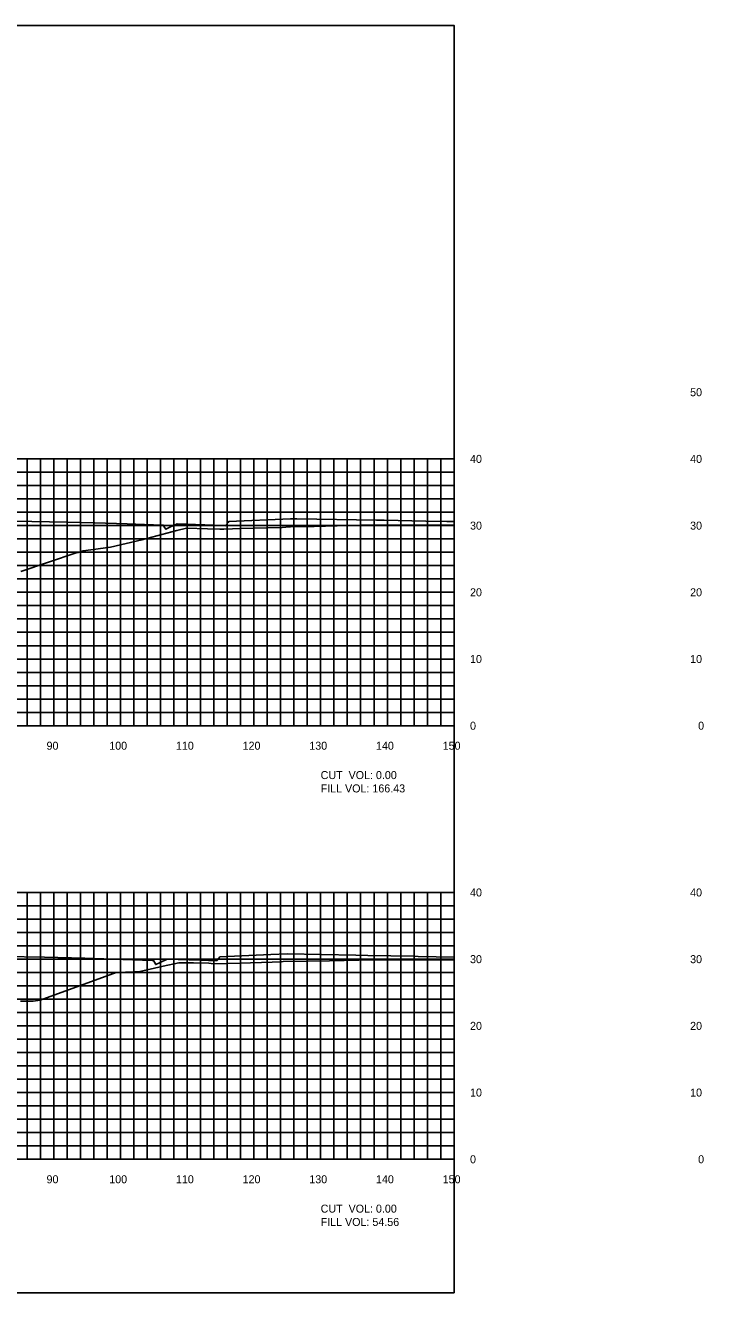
# Model space of a CAD drawing. Extents: x 1797518 to 1804843, y 248068 to 251132.
# Drawn here: x 1803736.7 to 1803838.4, y 250079.4 to 250269.4 of the extents above; entities that cross this region are included whole.
import ezdxf

# ---------------------------------------------------------------- set-up
doc = ezdxf.new("R2010")
doc.units = 0
for name, color, linetype in [('10', 7, 'Continuous'), ('31', 7, 'Continuous'), ('60', 7, 'Continuous'), ('ANNO-TXT', 7, 'Continuous'), ('CL-CNST', 7, 'Continuous'), ('Level 62', 7, 'Continuous'), ('M-ROADS', 7, 'Continuous')]:
    doc.layers.add(name, color=color, linetype=linetype)

msp = doc.modelspace()

# ---------------------------------------------------------------- linework, layer by layer
msp.add_lwpolyline([(1803501, 250079.43), (1803801, 250079.43), (1803801, 250269.43), (1803501, 250269.43)], close=True)
at = {"layer": '60'}
for p, q in [((1803801, 250164.43), (1803801, 250204.43)), ((1803801.06, 250204.43), (1803801, 250204.43)), ((1803801.06, 250194.43), (1803801, 250194.43)), ((1803801.06, 250184.43), (1803801, 250184.43)), ((1803801.06, 250174.43), (1803801, 250174.43)), ((1803501, 250164.43), (1803801, 250164.43)), ((1803741, 250164.37), (1803741, 250164.43)), ((1803751, 250164.37), (1803751, 250164.43)), ((1803761, 250164.37), (1803761, 250164.43)), ((1803771, 250164.37), (1803771, 250164.43)), ((1803781, 250164.37), (1803781, 250164.43)), ((1803791, 250164.37), (1803791, 250164.43)), ((1803801, 250164.37), (1803801, 250164.43)), ((1803801.06, 250164.43), (1803801, 250164.43)), ((1803801, 250099.43), (1803801, 250139.43)), ((1803801.06, 250139.43), (1803801, 250139.43)), ((1803801.06, 250129.43), (1803801, 250129.43)), ((1803801.06, 250119.43), (1803801, 250119.43)), ((1803801.06, 250109.43), (1803801, 250109.43)), ((1803501, 250099.43), (1803801, 250099.43)), ((1803741, 250099.37), (1803741, 250099.43)), ((1803751, 250099.37), (1803751, 250099.43)), ((1803761, 250099.37), (1803761, 250099.43)), ((1803771, 250099.37), (1803771, 250099.43)), ((1803781, 250099.37), (1803781, 250099.43)), ((1803791, 250099.37), (1803791, 250099.43)), ((1803801, 250099.37), (1803801, 250099.43)), ((1803801.06, 250099.43), (1803801, 250099.43))]:
    msp.add_line(p, q, dxfattribs=at)
at = {"layer": 'CL-CNST'}
for points in [[(1803735.03, 250195.08), (1803742.97, 250194.94), (1803747.14, 250194.86), (1803751.98, 250194.68), (1803757.22, 250194.49), (1803757.3, 250194.49), (1803757.44, 250194.48), (1803757.56, 250194.26), (1803757.77, 250193.88), (1803758.38, 250194.18), (1803759.49, 250194.71), (1803765.04, 250194.49), (1803766.67, 250194.42), (1803767.11, 250194.92), (1803767.21, 250195.04), (1803776.48, 250195.43), (1803777.28, 250195.47), (1803777.41, 250195.46), (1803789.36, 250195.26), (1803790.5, 250195.24), (1803796.75, 250195.12), (1803799.93, 250195.07), (1803801, 250195.05)], [(1803733.53, 250129.82), (1803739.57, 250129.71), (1803745.64, 250129.59), (1803749.89, 250129.44), (1803755.74, 250129.23), (1803755.82, 250129.22), (1803755.95, 250129.22), (1803756.08, 250128.99), (1803756.28, 250128.62), (1803756.92, 250128.92), (1803758.01, 250129.45), (1803762.92, 250129.26), (1803765.36, 250129.17), (1803765.74, 250129.6), (1803765.9, 250129.79), (1803773.52, 250130.11), (1803775.98, 250130.22), (1803786.28, 250130.03), (1803788.06, 250129.99), (1803794.99, 250129.87), (1803795.62, 250129.85), (1803801, 250129.75)]]:
    msp.add_lwpolyline(points, dxfattribs=at)
at = {"layer": 'Level 62'}
for p, q in [((1803501, 250204.43), (1803801, 250204.43)), ((1803737, 250164.43), (1803737, 250204.43)), ((1803739, 250164.43), (1803739, 250204.43)), ((1803741, 250164.43), (1803741, 250204.43)), ((1803743, 250164.43), (1803743, 250204.43)), ((1803745, 250164.43), (1803745, 250204.43)), ((1803747, 250164.43), (1803747, 250204.43)), ((1803749, 250164.43), (1803749, 250204.43)), ((1803751, 250164.43), (1803751, 250204.43)), ((1803753, 250164.43), (1803753, 250204.43)), ((1803755, 250164.43), (1803755, 250204.43)), ((1803757, 250164.43), (1803757, 250204.43)), ((1803759, 250164.43), (1803759, 250204.43)), ((1803761, 250164.43), (1803761, 250204.43)), ((1803763, 250164.43), (1803763, 250204.43)), ((1803765, 250164.43), (1803765, 250204.43)), ((1803767, 250164.43), (1803767, 250204.43)), ((1803769, 250164.43), (1803769, 250204.43)), ((1803771, 250164.43), (1803771, 250204.43)), ((1803773, 250164.43), (1803773, 250204.43)), ((1803775, 250164.43), (1803775, 250204.43)), ((1803777, 250164.43), (1803777, 250204.43)), ((1803779, 250164.43), (1803779, 250204.43)), ((1803781, 250164.43), (1803781, 250204.43)), ((1803783, 250164.43), (1803783, 250204.43)), ((1803785, 250164.43), (1803785, 250204.43)), ((1803787, 250164.43), (1803787, 250204.43)), ((1803789, 250164.43), (1803789, 250204.43)), ((1803791, 250164.43), (1803791, 250204.43)), ((1803793, 250164.43), (1803793, 250204.43)), ((1803795, 250164.43), (1803795, 250204.43)), ((1803797, 250164.43), (1803797, 250204.43)), ((1803799, 250164.43), (1803799, 250204.43)), ((1803801, 250164.43), (1803801, 250204.43)), ((1803501, 250202.43), (1803801, 250202.43)), ((1803501, 250200.43), (1803801, 250200.43)), ((1803501, 250198.43), (1803801, 250198.43)), ((1803501, 250196.43), (1803801, 250196.43)), ((1803501, 250194.43), (1803801, 250194.43)), ((1803501, 250192.43), (1803801, 250192.43)), ((1803501, 250190.43), (1803801, 250190.43)), ((1803501, 250188.43), (1803801, 250188.43)), ((1803501, 250186.43), (1803801, 250186.43)), ((1803501, 250184.43), (1803801, 250184.43)), ((1803501, 250182.43), (1803801, 250182.43)), ((1803501, 250180.43), (1803801, 250180.43)), ((1803501, 250178.43), (1803801, 250178.43)), ((1803501, 250176.43), (1803801, 250176.43)), ((1803501, 250174.43), (1803801, 250174.43)), ((1803501, 250172.43), (1803801, 250172.43)), ((1803501, 250170.43), (1803801, 250170.43)), ((1803501, 250168.43), (1803801, 250168.43)), ((1803501, 250166.43), (1803801, 250166.43)), ((1803501, 250164.43), (1803801, 250164.43)), ((1803501, 250139.43), (1803801, 250139.43)), ((1803737, 250099.43), (1803737, 250139.43)), ((1803739, 250099.43), (1803739, 250139.43)), ((1803741, 250099.43), (1803741, 250139.43)), ((1803743, 250099.43), (1803743, 250139.43)), ((1803745, 250099.43), (1803745, 250139.43)), ((1803747, 250099.43), (1803747, 250139.43)), ((1803749, 250099.43), (1803749, 250139.43)), ((1803751, 250099.43), (1803751, 250139.43)), ((1803753, 250099.43), (1803753, 250139.43)), ((1803755, 250099.43), (1803755, 250139.43)), ((1803757, 250099.43), (1803757, 250139.43)), ((1803759, 250099.43), (1803759, 250139.43)), ((1803761, 250099.43), (1803761, 250139.43)), ((1803763, 250099.43), (1803763, 250139.43)), ((1803765, 250099.43), (1803765, 250139.43)), ((1803767, 250099.43), (1803767, 250139.43)), ((1803769, 250099.43), (1803769, 250139.43)), ((1803771, 250099.43), (1803771, 250139.43)), ((1803773, 250099.43), (1803773, 250139.43)), ((1803775, 250099.43), (1803775, 250139.43)), ((1803777, 250099.43), (1803777, 250139.43)), ((1803779, 250099.43), (1803779, 250139.43)), ((1803781, 250099.43), (1803781, 250139.43)), ((1803783, 250099.43), (1803783, 250139.43)), ((1803785, 250099.43), (1803785, 250139.43)), ((1803787, 250099.43), (1803787, 250139.43)), ((1803789, 250099.43), (1803789, 250139.43)), ((1803791, 250099.43), (1803791, 250139.43)), ((1803793, 250099.43), (1803793, 250139.43)), ((1803795, 250099.43), (1803795, 250139.43)), ((1803797, 250099.43), (1803797, 250139.43)), ((1803799, 250099.43), (1803799, 250139.43)), ((1803801, 250099.43), (1803801, 250139.43)), ((1803501, 250137.43), (1803801, 250137.43)), ((1803501, 250135.43), (1803801, 250135.43)), ((1803501, 250133.43), (1803801, 250133.43)), ((1803501, 250131.43), (1803801, 250131.43)), ((1803501, 250129.43), (1803801, 250129.43)), ((1803501, 250127.43), (1803801, 250127.43)), ((1803501, 250125.43), (1803801, 250125.43)), ((1803501, 250123.43), (1803801, 250123.43)), ((1803501, 250121.43), (1803801, 250121.43)), ((1803501, 250119.43), (1803801, 250119.43)), ((1803501, 250117.43), (1803801, 250117.43)), ((1803501, 250115.43), (1803801, 250115.43)), ((1803501, 250113.43), (1803801, 250113.43)), ((1803501, 250111.43), (1803801, 250111.43)), ((1803501, 250109.43), (1803801, 250109.43)), ((1803501, 250107.43), (1803801, 250107.43)), ((1803501, 250105.43), (1803801, 250105.43)), ((1803501, 250103.43), (1803801, 250103.43)), ((1803501, 250101.43), (1803801, 250101.43)), ((1803501, 250099.43), (1803801, 250099.43))]:
    msp.add_line(p, q, dxfattribs=at)
at = {"layer": 'M-ROADS'}
for points in [[(1803736.04, 250187.56), (1803744.32, 250190.34), (1803744.62, 250190.38), (1803745.4, 250190.66), (1803745.78, 250190.71), (1803749.47, 250191.2), (1803754.2, 250192.3), (1803759.42, 250193.68), (1803760.89, 250194.04), (1803764.01, 250193.97), (1803765.88, 250193.92), (1803766.46, 250193.9), (1803769.08, 250193.98), (1803772.96, 250194.11), (1803775.22, 250194.17), (1803775.79, 250194.19), (1803776.48, 250194.23), (1803780.04, 250194.31), (1803785.18, 250194.43), (1803787, 250194.48), (1803788.23, 250194.5), (1803797.01, 250194.5), (1803800.42, 250194.51), (1803801, 250194.51)], [(1803735.97, 250123.12), (1803737.87, 250123.12), (1803738.93, 250123.3), (1803750.35, 250127.41), (1803753.16, 250127.55), (1803753.42, 250127.55), (1803753.68, 250127.55), (1803757.4, 250128.38), (1803759.75, 250128.9), (1803760.83, 250128.9), (1803761.92, 250128.9), (1803764.24, 250128.82), (1803764.95, 250128.73), (1803768.89, 250128.85), (1803773.72, 250129), (1803774.94, 250129.05), (1803774.98, 250129.05), (1803775.14, 250129.05), (1803775.4, 250129.06), (1803782.35, 250129.19), (1803786.75, 250129.3), (1803790.38, 250129.32), (1803798.94, 250129.33), (1803799.94, 250129.32), (1803801, 250129.31)]]:
    msp.add_lwpolyline(points, dxfattribs=at)

# ---------------------------------------------------------------- texts
at = {"layer": '10'}
for s, p in [('90', (1803739.9, 250160.83)), ('100', (1803749.3, 250160.83)), ('110', (1803759.3, 250160.83)), ('120', (1803769.3, 250160.83)), ('130', (1803779.3, 250160.83)), ('140', (1803789.3, 250160.83)), ('150', (1803799.3, 250160.83)), ('90', (1803739.9, 250095.83)), ('100', (1803749.3, 250095.83)), ('110', (1803759.3, 250095.83)), ('120', (1803769.3, 250095.83)), ('130', (1803779.3, 250095.83)), ('140', (1803789.3, 250095.83)), ('150', (1803799.3, 250095.83))]:
    msp.add_text(s, height=1.2, dxfattribs=at).set_placement(p)
at = {"layer": '31'}
for s, p in [('50', (1803836.4, 250213.83)), ('40', (1803803.4, 250203.83)), ('40', (1803836.4, 250203.83)), ('30', (1803803.4, 250193.83)), ('30', (1803836.4, 250193.83)), ('20', (1803803.4, 250183.83)), ('20', (1803836.4, 250183.83)), ('10', (1803803.4, 250173.83)), ('10', (1803836.4, 250173.83)), ('0', (1803803.4, 250163.83)), ('0', (1803837.6, 250163.83)), ('40', (1803803.4, 250138.83)), ('40', (1803836.4, 250138.83)), ('30', (1803803.4, 250128.83)), ('30', (1803836.4, 250128.83)), ('20', (1803803.4, 250118.83)), ('20', (1803836.4, 250118.83)), ('10', (1803803.4, 250108.83)), ('10', (1803836.4, 250108.83)), ('0', (1803803.4, 250098.83)), ('0', (1803837.6, 250098.83))]:
    msp.add_text(s, height=1.2, dxfattribs=at).set_placement(p)
at = {"layer": 'ANNO-TXT'}
for s, p in [('CUT  VOL: 0.00', (1803781, 250156.43)), ('FILL VOL: 166.43', (1803781, 250154.43)), ('CUT  VOL: 0.00', (1803781, 250091.43)), ('FILL VOL: 54.56', (1803781, 250089.43))]:
    msp.add_text(s, height=1.2, dxfattribs=at).set_placement(p)

doc.saveas('drawing.dxf')
